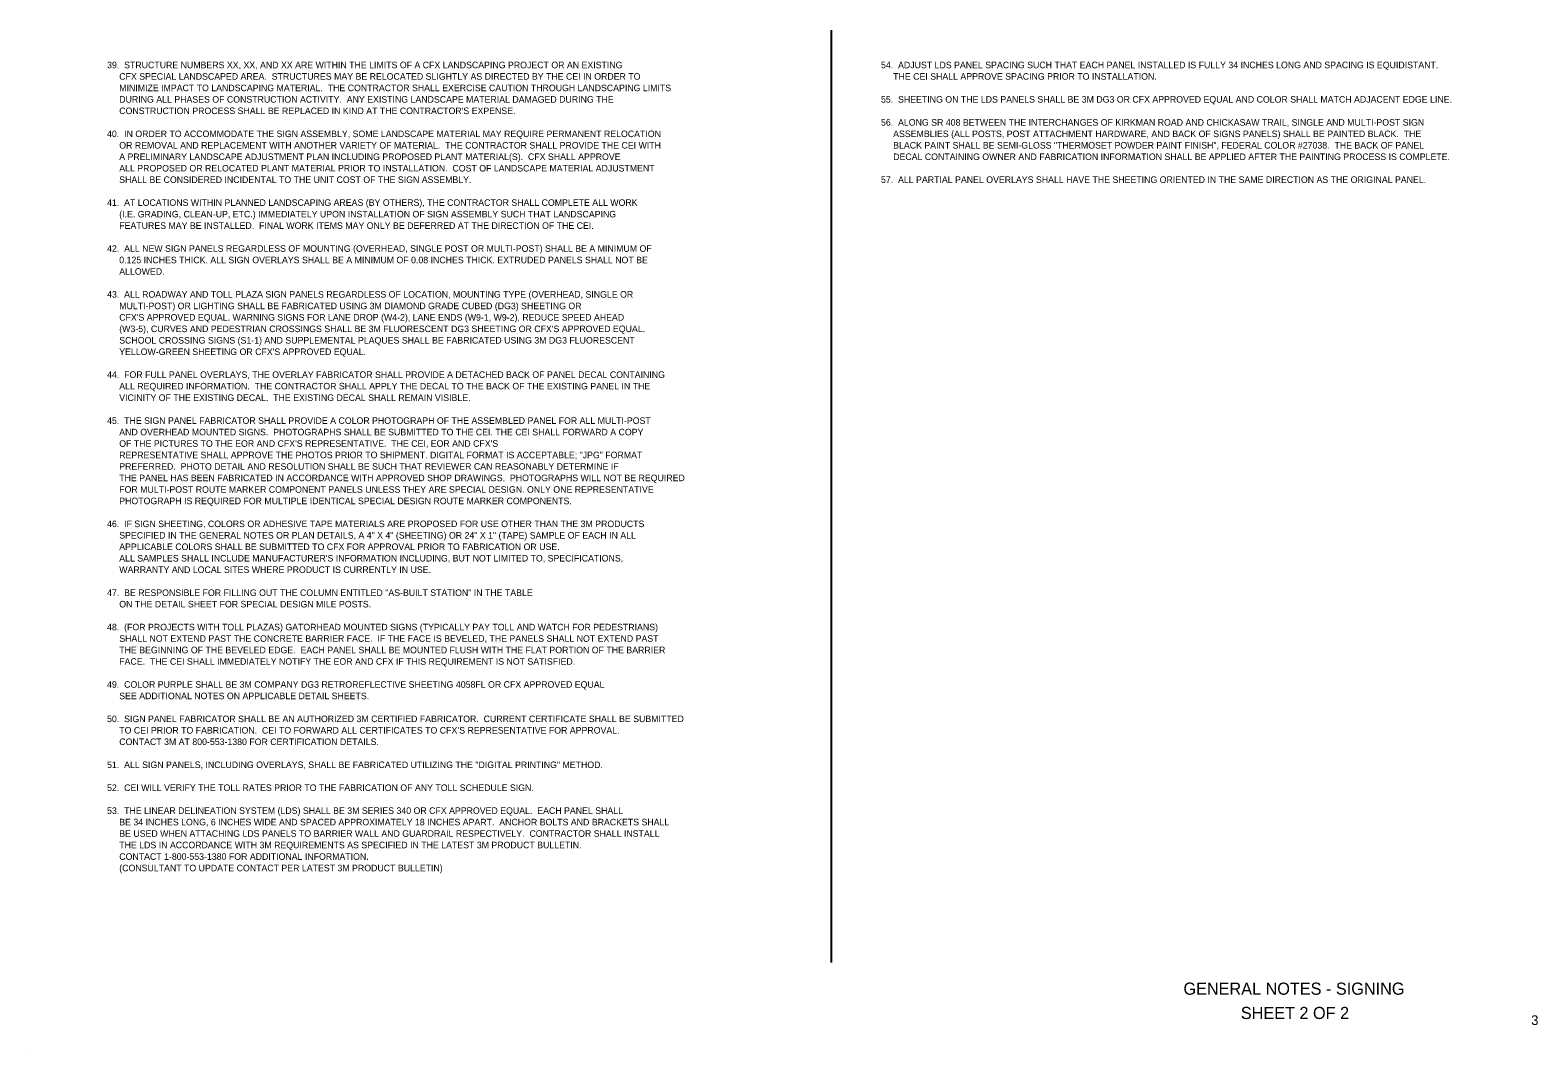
# Model space of a CAD drawing. Extents: x 2479953 to 2481505, y 3678869 to 3679919.
import ezdxf

# ---------------------------------------------------------------- set-up
doc = ezdxf.new("R2010")
doc.units = 0
for name, color, linetype in [('AdhocPoint_dp', 7, 'Continuous'), ('NonPlottingEle_dp', 7, 'Continuous'), ('TextLabel', 7, 'Continuous'), ('TextMisc', 7, 'Continuous'), ('TextShtNo', 7, 'Continuous')]:
    doc.layers.add(name, color=color, linetype=linetype)

msp = doc.modelspace()

# ---------------------------------------------------------------- linework, layer by layer
at = {"layer": 'AdhocPoint_dp'}
msp.add_line((2479952.6, 3678869), (2479952.6, 3678869), dxfattribs=at)
at = {"layer": 'NonPlottingEle_dp'}
msp.add_line((2480777.6, 3678959), (2480777.6, 3679919), dxfattribs=at)

# ---------------------------------------------------------------- texts
at = {"layer": 'TextLabel'}
for s, p in [('39.  STRUCTURE NUMBERS XX, XX, AND XX ARE WITHIN THE LIMITS OF A CFX LANDSCAPING PROJECT OR AN EXISTING', (2480031.8, 3679879.8)), ('54.  ADJUST LDS PANEL SPACING SUCH THAT EACH PANEL INSTALLED IS FULLY 34 INCHES LONG AND SPACING IS EQUIDISTANT.', (2480828.6, 3679879.8)), ('     CFX SPECIAL LANDSCAPED AREA.  STRUCTURES MAY BE RELOCATED SLIGHTLY AS DIRECTED BY THE CEI IN ORDER TO ', (2480031.8, 3679868)), ('     THE CEI SHALL APPROVE SPACING PRIOR TO INSTALLATION.', (2480828.6, 3679868)), ('     MINIMIZE IMPACT TO LANDSCAPING MATERIAL.  THE CONTRACTOR SHALL EXERCISE CAUTION THROUGH LANDSCAPING LIMITS', (2480031.8, 3679856.2)), ('     DURING ALL PHASES OF CONSTRUCTION ACTIVITY.  ANY EXISTING LANDSCAPE MATERIAL DAMAGED DURING THE ', (2480031.8, 3679844.4)), ('55.  SHEETING ON THE LDS PANELS SHALL BE 3M DG3 OR CFX APPROVED EQUAL AND COLOR SHALL MATCH ADJACENT EDGE LINE.', (2480828.6, 3679844.4)), ("     CONSTRUCTION PROCESS SHALL BE REPLACED IN KIND AT THE CONTRACTOR'S EXPENSE.", (2480031.8, 3679832.6)), ('56.  ALONG SR 408 BETWEEN THE INTERCHANGES OF KIRKMAN ROAD AND CHICKASAW TRAIL, SINGLE AND MULTI-POST SIGN', (2480828.6, 3679820.7)), ('40.  IN ORDER TO ACCOMMODATE THE SIGN ASSEMBLY, SOME LANDSCAPE MATERIAL MAY REQUIRE PERMANENT RELOCATION', (2480031.8, 3679808.9)), ('     OR REMOVAL AND REPLACEMENT WITH ANOTHER VARIETY OF MATERIAL.  THE CONTRACTOR SHALL PROVIDE THE CEI WITH', (2480031.8, 3679797.1)), ('     ASSEMBLIES (ALL POSTS, POST ATTACHMENT HARDWARE, AND BACK OF SIGNS PANELS) SHALL BE PAINTED BLACK.  THE', (2480828.6, 3679808.9)), ('     BLACK PAINT SHALL BE SEMI-GLOSS "THERMOSET POWDER PAINT FINISH", FEDERAL COLOR #27038.  THE BACK OF PANEL', (2480828.6, 3679797.1)), ('     A PRELIMINARY LANDSCAPE ADJUSTMENT PLAN INCLUDING PROPOSED PLANT MATERIAL(S).  CFX SHALL APPROVE', (2480031.8, 3679785.3)), ('     DECAL CONTAINING OWNER AND FABRICATION INFORMATION SHALL BE APPLIED AFTER THE PAINTING PROCESS IS COMPLETE.', (2480828.6, 3679785.3)), ('     ALL PROPOSED OR RELOCATED PLANT MATERIAL PRIOR TO INSTALLATION.  COST OF LANDSCAPE MATERIAL ADJUSTMENT', (2480031.8, 3679773.5)), ('     SHALL BE CONSIDERED INCIDENTAL TO THE UNIT COST OF THE SIGN ASSEMBLY.', (2480031.8, 3679761.7)), ('57.  ALL PARTIAL PANEL OVERLAYS SHALL HAVE THE SHEETING ORIENTED IN THE SAME DIRECTION AS THE ORIGINAL PANEL.', (2480828.6, 3679761.7)), ('41.  AT LOCATIONS WITHIN PLANNED LANDSCAPING AREAS (BY OTHERS), THE CONTRACTOR SHALL COMPLETE ALL WORK', (2480031.8, 3679738.1)), ('     (I.E. GRADING, CLEAN-UP, ETC.) IMMEDIATELY UPON INSTALLATION OF SIGN ASSEMBLY SUCH THAT LANDSCAPING ', (2480031.8, 3679726.2)), ('     FEATURES MAY BE INSTALLED.  FINAL WORK ITEMS MAY ONLY BE DEFERRED AT THE DIRECTION OF THE CEI.', (2480031.8, 3679714.4)), ('42.  ALL NEW SIGN PANELS REGARDLESS OF MOUNTING (OVERHEAD, SINGLE POST OR MULTI-POST) SHALL BE A MINIMUM OF', (2480031.8, 3679690.8)), ('     0.125 INCHES THICK. ALL SIGN OVERLAYS SHALL BE A MINIMUM OF 0.08 INCHES THICK. EXTRUDED PANELS SHALL NOT BE ', (2480031.8, 3679679)), ('     ALLOWED.', (2480031.8, 3679667.2)), ('43.  ALL ROADWAY AND TOLL PLAZA SIGN PANELS REGARDLESS OF LOCATION, MOUNTING TYPE (OVERHEAD, SINGLE OR ', (2480031.8, 3679643.6)), ('     MULTI-POST) OR LIGHTING SHALL BE FABRICATED USING 3M DIAMOND GRADE CUBED (DG3) SHEETING OR', (2480031.8, 3679631.7)), ("     CFX'S APPROVED EQUAL. WARNING SIGNS FOR LANE DROP (W4-2), LANE ENDS (W9-1, W9-2), REDUCE SPEED AHEAD", (2480031.8, 3679619.9)), ('     SCHOOL CROSSING SIGNS (S1-1) AND SUPPLEMENTAL PLAQUES SHALL BE FABRICATED USING 3M DG3 FLUORESCENT ', (2480031.8, 3679596.3)), ("     (W3-5), CURVES AND PEDESTRIAN CROSSINGS SHALL BE 3M FLUORESCENT DG3 SHEETING OR CFX'S APPROVED EQUAL.", (2480031.8, 3679608.1)), ("     YELLOW-GREEN SHEETING OR CFX'S APPROVED EQUAL.", (2480031.8, 3679584.5)), ('44.  FOR FULL PANEL OVERLAYS, THE OVERLAY FABRICATOR SHALL PROVIDE A DETACHED BACK OF PANEL DECAL CONTAINING', (2480031.8, 3679560.9)), ('     ALL REQUIRED INFORMATION.  THE CONTRACTOR SHALL APPLY THE DECAL TO THE BACK OF THE EXISTING PANEL IN THE', (2480031.8, 3679549.1)), ('     VICINITY OF THE EXISTING DECAL.  THE EXISTING DECAL SHALL REMAIN VISIBLE.', (2480031.8, 3679537.2)), ('45.  THE SIGN PANEL FABRICATOR SHALL PROVIDE A COLOR PHOTOGRAPH OF THE ASSEMBLED PANEL FOR ALL MULTI-POST ', (2480031.8, 3679513.6)), ('     AND OVERHEAD MOUNTED SIGNS.  PHOTOGRAPHS SHALL BE SUBMITTED TO THE CEI. THE CEI SHALL FORWARD A COPY', (2480031.8, 3679501.8)), ("     OF THE PICTURES TO THE EOR AND CFX'S REPRESENTATIVE.  THE CEI, EOR AND CFX'S ", (2480031.8, 3679490)), ('     REPRESENTATIVE SHALL APPROVE THE PHOTOS PRIOR TO SHIPMENT. DIGITAL FORMAT IS ACCEPTABLE; "JPG" FORMAT ', (2480031.8, 3679478.2)), ('     THE PANEL HAS BEEN FABRICATED IN ACCORDANCE WITH APPROVED SHOP DRAWINGS.  PHOTOGRAPHS WILL NOT BE REQUIRED ', (2480031.8, 3679454.6)), ('     PREFERRED.  PHOTO DETAIL AND RESOLUTION SHALL BE SUCH THAT REVIEWER CAN REASONABLY DETERMINE IF', (2480031.8, 3679466.4)), ('     FOR MULTI-POST ROUTE MARKER COMPONENT PANELS UNLESS THEY ARE SPECIAL DESIGN. ONLY ONE REPRESENTATIVE ', (2480031.8, 3679442.7)), ('     PHOTOGRAPH IS REQUIRED FOR MULTIPLE IDENTICAL SPECIAL DESIGN ROUTE MARKER COMPONENTS.', (2480031.8, 3679430.9)), ('46.  IF SIGN SHEETING, COLORS OR ADHESIVE TAPE MATERIALS ARE PROPOSED FOR USE OTHER THAN THE 3M PRODUCTS ', (2480031.8, 3679407.3)), ('     SPECIFIED IN THE GENERAL NOTES OR PLAN DETAILS, A 4" X 4" (SHEETING) OR 24" X 1" (TAPE) SAMPLE OF EACH IN ALL', (2480031.8, 3679395.5)), ('     APPLICABLE COLORS SHALL BE SUBMITTED TO CFX FOR APPROVAL PRIOR TO FABRICATION OR USE.  ', (2480031.8, 3679383.7)), ("     ALL SAMPLES SHALL INCLUDE MANUFACTURER'S INFORMATION INCLUDING, BUT NOT LIMITED TO, SPECIFICATIONS, ", (2480031.8, 3679371.9)), ('     WARRANTY AND LOCAL SITES WHERE PRODUCT IS CURRENTLY IN USE.', (2480031.8, 3679360.1)), ('47.  BE RESPONSIBLE FOR FILLING OUT THE COLUMN ENTITLED "AS-BUILT STATION" IN THE TABLE ', (2480031.8, 3679336.4)), ('     ON THE DETAIL SHEET FOR SPECIAL DESIGN MILE POSTS.', (2480031.8, 3679324.6)), ('48.  (FOR PROJECTS WITH TOLL PLAZAS) GATORHEAD MOUNTED SIGNS (TYPICALLY PAY TOLL AND WATCH FOR PEDESTRIANS)', (2480031.8, 3679301)), ('     SHALL NOT EXTEND PAST THE CONCRETE BARRIER FACE.  IF THE FACE IS BEVELED, THE PANELS SHALL NOT EXTEND PAST', (2480031.8, 3679289.2)), ('     THE BEGINNING OF THE BEVELED EDGE.  EACH PANEL SHALL BE MOUNTED FLUSH WITH THE FLAT PORTION OF THE BARRIER', (2480031.8, 3679277.4)), ('     FACE.  THE CEI SHALL IMMEDIATELY NOTIFY THE EOR AND CFX IF THIS REQUIREMENT IS NOT SATISFIED.', (2480031.8, 3679265.6)), ('49.  COLOR PURPLE SHALL BE 3M COMPANY DG3 RETROREFLECTIVE SHEETING 4058FL OR CFX APPROVED EQUAL', (2480031.8, 3679241.9)), ('     SEE ADDITIONAL NOTES ON APPLICABLE DETAIL SHEETS.', (2480031.8, 3679230.1)), ('50.  SIGN PANEL FABRICATOR SHALL BE AN AUTHORIZED 3M CERTIFIED FABRICATOR.  CURRENT CERTIFICATE SHALL BE SUBMITTED', (2480031.8, 3679206.5)), ('     TO CEI PRIOR TO FABRICATION.  CEI TO FORWARD ALL CERTIFICATES TO CFX’S REPRESENTATIVE FOR APPROVAL.', (2480031.8, 3679194.7)), ('     CONTACT 3M AT 800-553-1380 FOR CERTIFICATION DETAILS.', (2480031.8, 3679182.9)), ('51.  ALL SIGN PANELS, INCLUDING OVERLAYS, SHALL BE FABRICATED UTILIZING THE "DIGITAL PRINTING" METHOD.', (2480031.8, 3679159.2)), ('52.  CEI WILL VERIFY THE TOLL RATES PRIOR TO THE FABRICATION OF ANY TOLL SCHEDULE SIGN.', (2480031.8, 3679135.6)), ('53.  THE LINEAR DELINEATION SYSTEM (LDS) SHALL BE 3M SERIES 340 OR CFX APPROVED EQUAL.  EACH PANEL SHALL', (2480031.8, 3679112)), ('     BE 34 INCHES LONG, 6 INCHES WIDE AND SPACED APPROXIMATELY 18 INCHES APART.  ANCHOR BOLTS AND BRACKETS SHALL', (2480031.8, 3679100.2)), ('     BE USED WHEN ATTACHING LDS PANELS TO BARRIER WALL AND GUARDRAIL RESPECTIVELY.  CONTRACTOR SHALL INSTALL', (2480031.8, 3679088.4)), ('     THE LDS IN ACCORDANCE WITH 3M REQUIREMENTS AS SPECIFIED IN THE LATEST 3M PRODUCT BULLETIN.  ', (2480031.8, 3679076.6)), ('     CONTACT 1-800-553-1380 FOR ADDITIONAL INFORMATION.', (2480031.8, 3679064.7)), ('     (CONSULTANT TO UPDATE CONTACT PER LATEST 3M PRODUCT BULLETIN)', (2480031.8, 3679052.9))]:
    msp.add_text(s, height=6.75, dxfattribs=at).set_placement(p)
at = {"layer": 'TextMisc'}
for s, p in [('GENERAL NOTES - SIGNING ', (2481140, 3678925.8)), ('      SHEET 2 OF 2      ', (2481171.2, 3678900.8))]:
    msp.add_text(s, height=12.5, rotation=360, dxfattribs=at).set_placement(p)
at = {"layer": 'TextShtNo'}
msp.add_text('  3   ', height=10, rotation=360, dxfattribs=at).set_placement((2481490.6, 3678894.6))

doc.saveas('drawing.dxf')
